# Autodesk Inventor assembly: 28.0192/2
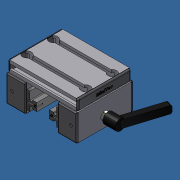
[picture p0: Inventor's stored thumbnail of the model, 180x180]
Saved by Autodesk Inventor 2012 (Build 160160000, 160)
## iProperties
Created: 2007-06
Part Number: 28.0192/2
Document SubType Name: Assembly
Designer: Andy Moles
Description: SLIDE LWN 32X45-45 WITH SIDE CLAMP
Mass: 796.055 g
Surface Area: 1985.86 cm^2
Volume: 307.746 cm^3
Density: 2.58673 g/cm^3
Author: Andy Moles
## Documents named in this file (12)
- C:\Andys Backup Data\ANDY'S INVENTOR\INVENTOR LIBRARIES\PARTS LIBRARY\READY FOR USE MODULES LG\28.0192_2 SLIDE LWN 32X45-45 WITH SIDE CLAMP.iam
- C:\Andys Backup Data\ANDY'S INVENTOR\INVENTOR LIBRARIES\PARTS LIBRARY\READY FOR USE MODULES LG\SUBCOMPONENTS\28.0222 SLIDE LWN 32X45-45 90X19.ipt
- C:\Andys Backup Data\ANDY'S INVENTOR\INVENTOR LIBRARIES\PARTS LIBRARY\READY FOR USE MODULES LG\SUBCOMPONENTS\28.0126 SLIDE 45X32.ipt
- C:\Andys Backup Data\ANDY'S INVENTOR\INVENTOR LIBRARIES\PARTS LIBRARY\COMPONENTS LG\22.1095 SLIDE RAIL LN.iam
- C:\Andys Backup Data\ANDY'S INVENTOR\INVENTOR LIBRARIES\PARTS LIBRARY\FASTENING ELEMENTS\SCREWS CAP\21.1200 M8X16.ipt
- C:\Andys Backup Data\ANDY'S INVENTOR\INVENTOR LIBRARIES\PARTS LIBRARY\FASTENING ELEMENTS\NUTS\21.1351 M8 SQUARE NUT.ipt
- C:\Andys Backup Data\ANDY'S INVENTOR\INVENTOR LIBRARIES\PARTS LIBRARY\COMPONENTS LG\22.1095_9 SLIDE RAIL LN FOR SIDE LOCK.iam
- C:\Andys Backup Data\ANDY'S INVENTOR\INVENTOR LIBRARIES\PARTS LIBRARY\READY FOR USE MODULES LG\SUBCOMPONENTS\28.0126_9 SIDE LOCK 45X32.ipt
- C:\Andys Backup Data\ANDY'S INVENTOR\INVENTOR LIBRARIES\PARTS LIBRARY\COMPONENTS LG\21.1014_2 SLIDE LOCK WITH M6X51 STUD.ipt
- C:\Andys Backup Data\ANDY'S INVENTOR\INVENTOR LIBRARIES\PARTS LIBRARY\FASTENING ELEMENTS\NUTS\21.1330 M6 SQUARE NUT.ipt
- C:\Andys Backup Data\ANDY'S INVENTOR\INVENTOR LIBRARIES\PARTS LIBRARY\END CAPS\22.1014_1 END CAP 90X19 GRAY.ipt
- C:\Andys Backup Data\ANDY'S INVENTOR\INVENTOR LIBRARIES\PARTS LIBRARY\END CAPS\22.1003_1 END CAP 45x32 Z Gray.iam
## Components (21 placed, 11 different names)
1. 28.0222 SLIDE LWN 32X45-45 90X19:1 — Mate:1, Mate:2, Flush:1, Mate:4, Flush:4, Flush:5, Flush:18, Flush:19, Insert:1, Insert:2, Insert:3, Insert:4, Insert:5, Insert:6, Insert:7, Insert:8, Mate:15, Flush:20, Flush:21, Mate:21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
2. 28.0126 SLIDE 45X32:2 — Mate:4, Flush:4, Flush:5, Mate:13, Mate:14, Mate:24, Flush:30, Flush:31, Mate:26, Flush:34, Flush:35
3. 22.1014_1 END CAP 90X19 GRAY:1 — Mate:22, Flush:26, Flush:27
4. 22.1014_1 END CAP 90X19 GRAY:2 — Mate:21, Flush:24, Flush:25
5. 22.1095_9 SLIDE RAIL LN FOR SIDE LOCK:1 [sub-assembly] — Flush:18, Mate:17, Mate:19, Mate:20
6. 22.1095 SLIDE RAIL LN:3 [sub-assembly] — Mate:13, Flush:19, Mate:14
7. 21.1200 M8 x 16:1 — Insert:1
8. 21.1200 M8 x 16:2 — Insert:2
9. 21.1200 M8 x 16:3 — Insert:3
10. 21.1200 M8 x 16:4 — Insert:4
11. 21.1351 M8 SQUARE NUT:1 — Insert:5
12. 21.1351 M8 SQUARE NUT:2 — Insert:6
13. 21.1351 M8 SQUARE NUT:3 — Insert:8
14. 21.1351 M8 SQUARE NUT:4 — Insert:7
15. 28.0126_9 SIDE LOCK 45X32:1 — Mate:15, Flush:20, Flush:21, Insert:9, Mate:19, Mate:20, Mate:23, Flush:28, Flush:29, Mate:25, Flush:32, Flush:33
16. 21.1014_2 SLIDE LOCK WITH M6X51 STUD:1 — Insert:9, Mate:16
17. 21.1330 M6 SQUARE NUT:1 — Mate:16, Mate:17
18. 22.1003_1 END CAP 45x32 Z Gray:1 [sub-assembly] — Mate:24, Flush:30, Flush:31
19. 22.1003_1 END CAP 45x32 Z Gray:2 [sub-assembly] — Mate:23, Flush:28, Flush:29
20. 22.1003_1 END CAP 45x32 Z Gray:3 [sub-assembly] — Mate:26, Flush:34, Flush:35
21. 22.1003_1 END CAP 45x32 Z Gray:4 [sub-assembly] — Mate:25, Flush:32, Flush:33
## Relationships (44: Flush 19, Mate 16, Insert 9)
- Mate:1: 28.0222 SLIDE LWN 32X45-45 90X19:1
- Mate:2: 28.0222 SLIDE LWN 32X45-45 90X19:1
- Flush:1: 28.0222 SLIDE LWN 32X45-45 90X19:1
- Mate:4: 28.0222 SLIDE LWN 32X45-45 90X19:1 ↔ 28.0126 SLIDE 45X32:2
- Flush:4: 28.0222 SLIDE LWN 32X45-45 90X19:1 ↔ 28.0126 SLIDE 45X32:2
- Flush:5: 28.0222 SLIDE LWN 32X45-45 90X19:1 ↔ 28.0126 SLIDE 45X32:2
- Flush:18: 28.0222 SLIDE LWN 32X45-45 90X19:1 ↔ 22.1095_9 SLIDE RAIL LN FOR SIDE LOCK:1
- Mate:13: 28.0126 SLIDE 45X32:2 ↔ 22.1095 SLIDE RAIL LN:3
- Flush:19: 28.0222 SLIDE LWN 32X45-45 90X19:1 ↔ 22.1095 SLIDE RAIL LN:3
- Mate:14: 28.0126 SLIDE 45X32:2 ↔ 22.1095 SLIDE RAIL LN:3
- Insert:1: 28.0222 SLIDE LWN 32X45-45 90X19:1 ↔ 21.1200 M8 x 16:1
- Insert:2: 28.0222 SLIDE LWN 32X45-45 90X19:1 ↔ 21.1200 M8 x 16:2
- Insert:3: 28.0222 SLIDE LWN 32X45-45 90X19:1 ↔ 21.1200 M8 x 16:3
- Insert:4: 28.0222 SLIDE LWN 32X45-45 90X19:1 ↔ 21.1200 M8 x 16:4
- Insert:5: 28.0222 SLIDE LWN 32X45-45 90X19:1 ↔ 21.1351 M8 SQUARE NUT:1
- Insert:6: 28.0222 SLIDE LWN 32X45-45 90X19:1 ↔ 21.1351 M8 SQUARE NUT:2
- Insert:7: 28.0222 SLIDE LWN 32X45-45 90X19:1 ↔ 21.1351 M8 SQUARE NUT:4
- Insert:8: 28.0222 SLIDE LWN 32X45-45 90X19:1 ↔ 21.1351 M8 SQUARE NUT:3
- Mate:15: 28.0222 SLIDE LWN 32X45-45 90X19:1 ↔ 28.0126_9 SIDE LOCK 45X32:1
- Flush:20: 28.0222 SLIDE LWN 32X45-45 90X19:1 ↔ 28.0126_9 SIDE LOCK 45X32:1
- Flush:21: 28.0222 SLIDE LWN 32X45-45 90X19:1 ↔ 28.0126_9 SIDE LOCK 45X32:1
- Insert:9: 28.0126_9 SIDE LOCK 45X32:1 ↔ 21.1014_2 SLIDE LOCK WITH M6X51 STUD:1
- Mate:16: 21.1014_2 SLIDE LOCK WITH M6X51 STUD:1 ↔ 21.1330 M6 SQUARE NUT:1
- Mate:17: 22.1095_9 SLIDE RAIL LN FOR SIDE LOCK:1 ↔ 21.1330 M6 SQUARE NUT:1
- Mate:19: 22.1095_9 SLIDE RAIL LN FOR SIDE LOCK:1 ↔ 28.0126_9 SIDE LOCK 45X32:1
- Mate:20: 22.1095_9 SLIDE RAIL LN FOR SIDE LOCK:1 ↔ 28.0126_9 SIDE LOCK 45X32:1
- Mate:21: 28.0222 SLIDE LWN 32X45-45 90X19:1 ↔ 22.1014_1 END CAP 90X19 GRAY:2
- Flush:24: 28.0222 SLIDE LWN 32X45-45 90X19:1 ↔ 22.1014_1 END CAP 90X19 GRAY:2
- Flush:25: 28.0222 SLIDE LWN 32X45-45 90X19:1 ↔ 22.1014_1 END CAP 90X19 GRAY:2
- Mate:22: 28.0222 SLIDE LWN 32X45-45 90X19:1 ↔ 22.1014_1 END CAP 90X19 GRAY:1
- Flush:26: 28.0222 SLIDE LWN 32X45-45 90X19:1 ↔ 22.1014_1 END CAP 90X19 GRAY:1
- Flush:27: 28.0222 SLIDE LWN 32X45-45 90X19:1 ↔ 22.1014_1 END CAP 90X19 GRAY:1
- Mate:23: 28.0126_9 SIDE LOCK 45X32:1 ↔ 22.1003_1 END CAP 45x32 Z Gray:2
- Flush:28: 28.0126_9 SIDE LOCK 45X32:1 ↔ 22.1003_1 END CAP 45x32 Z Gray:2
- Flush:29: 28.0126_9 SIDE LOCK 45X32:1 ↔ 22.1003_1 END CAP 45x32 Z Gray:2
- Mate:24: 28.0126 SLIDE 45X32:2 ↔ 22.1003_1 END CAP 45x32 Z Gray:1
- Flush:30: 28.0126 SLIDE 45X32:2 ↔ 22.1003_1 END CAP 45x32 Z Gray:1
- Flush:31: 28.0126 SLIDE 45X32:2 ↔ 22.1003_1 END CAP 45x32 Z Gray:1
- Mate:25: 28.0126_9 SIDE LOCK 45X32:1 ↔ 22.1003_1 END CAP 45x32 Z Gray:4
- Flush:32: 28.0126_9 SIDE LOCK 45X32:1 ↔ 22.1003_1 END CAP 45x32 Z Gray:4
- Flush:33: 28.0126_9 SIDE LOCK 45X32:1 ↔ 22.1003_1 END CAP 45x32 Z Gray:4
- Mate:26: 28.0126 SLIDE 45X32:2 ↔ 22.1003_1 END CAP 45x32 Z Gray:3
- Flush:34: 28.0126 SLIDE 45X32:2 ↔ 22.1003_1 END CAP 45x32 Z Gray:3
- Flush:35: 28.0126 SLIDE 45X32:2 ↔ 22.1003_1 END CAP 45x32 Z Gray:3
